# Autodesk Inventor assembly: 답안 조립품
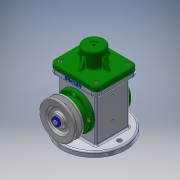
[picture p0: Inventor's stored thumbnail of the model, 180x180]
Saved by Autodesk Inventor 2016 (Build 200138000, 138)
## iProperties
Created: 2018-10
Part Number: 답안 조립품
Material: 일반
Document SubType Name: Assembly
Designer: USER
Author: USER
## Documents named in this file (18)
- C:\Users\USER\Desktop\481007V1027\답안 조립품.iam
- C:\Users\USER\Desktop\481007V1027\E-링.ipt
- C:\Users\USER\Desktop\481007V1027\V-벨트풀리.ipt
- C:\Users\USER\Desktop\481007V1027\덮개.ipt
- C:\Users\USER\Desktop\481007V1027\뒤커버.ipt
- C:\Users\USER\Desktop\481007V1027\링크.ipt
- C:\Users\USER\Desktop\481007V1027\베어링 17 x 40 x 12.ipt
- C:\Users\USER\Desktop\481007V1027\본체.ipt
- C:\Users\USER\Desktop\481007V1027\볼트 M4 x 8.ipt
- C:\Users\USER\Desktop\481007V1027\볼트 M4 x 10.ipt
- C:\Users\USER\Desktop\481007V1027\슬라이더.ipt
- C:\Users\USER\Desktop\481007V1027\앞커버.ipt
- C:\Users\USER\Desktop\481007V1027\오일 실 17 30 8.ipt
- C:\Users\USER\Desktop\481007V1027\와셔 4x16.ipt
- C:\Users\USER\Desktop\481007V1027\클레비스 핀 6 x 22.ipt
- 클레비스 핀 6 x 22.ipt
- C:\Users\USER\Desktop\481007V1027\키 4 x 4 x 12.ipt
- C:\Users\USER\Desktop\481007V1027\편심축.ipt
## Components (2 placed, 2 different names)
1. E-링:1
2. V-벨트풀리:1
